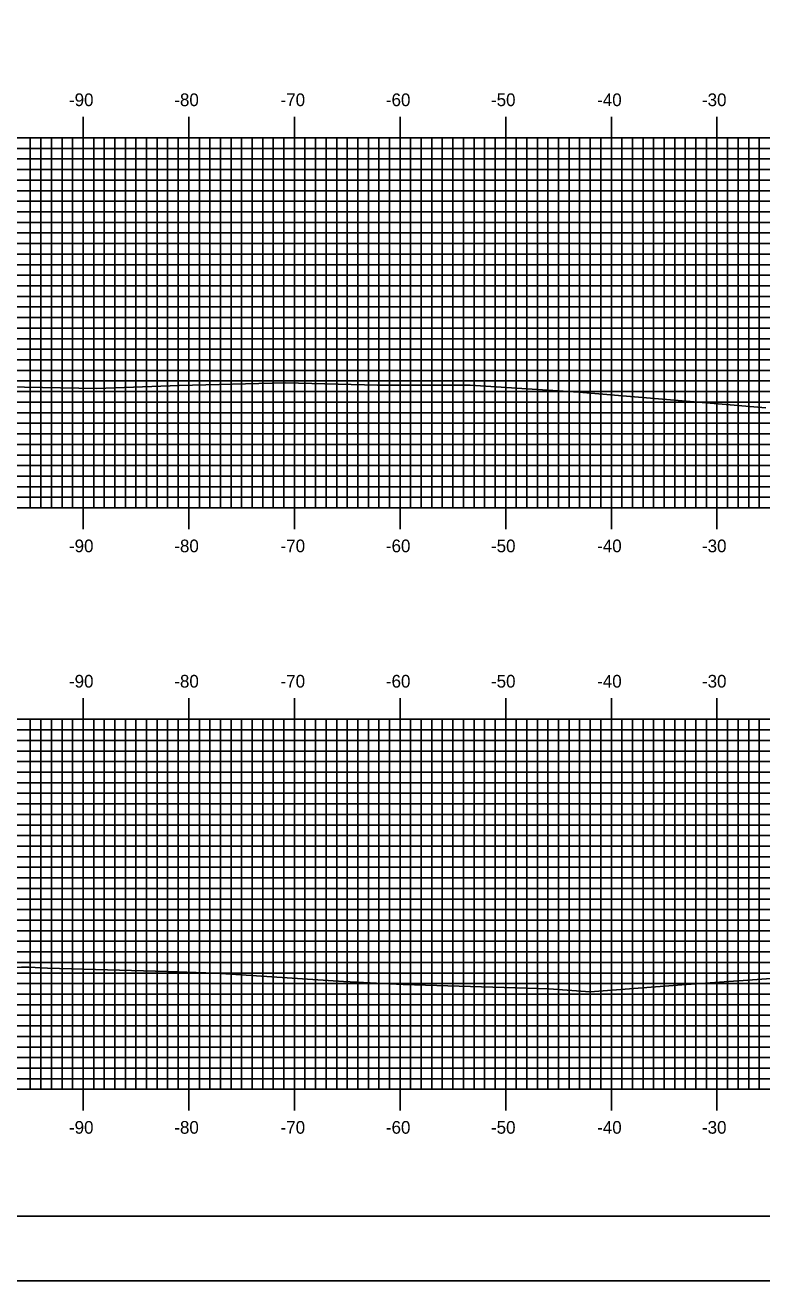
# Model space of a CAD drawing. Extents: x 853329 to 853673, y 364366 to 364586.
# Drawn here: x 853399.7 to 853469.5, y 364365.7 to 364484.5 of the extents above; entities that cross this region are included whole.
import ezdxf

# ---------------------------------------------------------------- set-up
doc = ezdxf.new("R2010")
doc.units = 0
for name, color, linetype in [('BORDER', 7, 'Continuous'), ('H_V ANNOTATION', 7, 'Continuous'), ('MAJOR', 7, 'Continuous'), ('MINOR', 7, 'Continuous'), ('PLOT BOUNDARY', 7, 'Continuous'), ('S_Roadway_Centerline', 7, 'Continuous')]:
    doc.layers.add(name, color=color, linetype=linetype)

msp = doc.modelspace()

# ---------------------------------------------------------------- linework, layer by layer
at = {"layer": 'BORDER'}
msp.add_lwpolyline([(853345.6, 364371.79), (853665.6, 364371.79), (853665.6, 364581.79), (853345.6, 364581.79)], close=True, dxfattribs=at)
at = {"layer": 'MAJOR'}
for p, q in [((853405.2, 364475.79), (853405.2, 364473.79)), ((853415.2, 364475.79), (853415.2, 364473.79)), ((853425.2, 364475.79), (853425.2, 364473.79)), ((853435.2, 364475.79), (853435.2, 364473.79)), ((853445.2, 364475.79), (853445.2, 364473.79)), ((853455.2, 364475.79), (853455.2, 364473.79)), ((853465.2, 364475.79), (853465.2, 364473.79)), ((853355.2, 364473.79), (853635.2, 364473.79)), ((853355.2, 364473.79), (853635.2, 364473.79)), ((853405.2, 364438.79), (853405.2, 364473.79)), ((853415.2, 364438.79), (853415.2, 364473.79)), ((853425.2, 364438.79), (853425.2, 364473.79)), ((853435.2, 364438.79), (853435.2, 364473.79)), ((853445.2, 364438.79), (853445.2, 364473.79)), ((853455.2, 364438.79), (853455.2, 364473.79)), ((853465.2, 364438.79), (853465.2, 364473.79)), ((853355.2, 364468.79), (853635.2, 364468.79)), ((853355.2, 364463.79), (853635.2, 364463.79)), ((853355.2, 364458.79), (853635.2, 364458.79)), ((853355.2, 364453.79), (853635.2, 364453.79)), ((853355.2, 364448.79), (853635.2, 364448.79)), ((853355.2, 364443.79), (853635.2, 364443.79)), ((853355.2, 364438.79), (853635.2, 364438.79)), ((853355.2, 364438.79), (853635.2, 364438.79)), ((853405.2, 364436.78), (853405.2, 364438.79)), ((853415.2, 364436.78), (853415.2, 364438.79)), ((853425.2, 364436.78), (853425.2, 364438.79)), ((853435.2, 364436.78), (853435.2, 364438.79)), ((853445.2, 364436.78), (853445.2, 364438.79)), ((853455.2, 364436.78), (853455.2, 364438.79)), ((853465.2, 364436.78), (853465.2, 364438.79)), ((853405.2, 364420.79), (853405.2, 364418.79)), ((853415.2, 364420.79), (853415.2, 364418.79)), ((853425.2, 364420.79), (853425.2, 364418.79)), ((853435.2, 364420.79), (853435.2, 364418.79)), ((853445.2, 364420.79), (853445.2, 364418.79)), ((853455.2, 364420.79), (853455.2, 364418.79)), ((853465.2, 364420.79), (853465.2, 364418.79)), ((853355.2, 364418.79), (853635.2, 364418.79)), ((853355.2, 364418.79), (853635.2, 364418.79)), ((853405.2, 364383.79), (853405.2, 364418.79)), ((853415.2, 364383.79), (853415.2, 364418.79)), ((853425.2, 364383.79), (853425.2, 364418.79)), ((853435.2, 364383.79), (853435.2, 364418.79)), ((853445.2, 364383.79), (853445.2, 364418.79)), ((853455.2, 364383.79), (853455.2, 364418.79)), ((853465.2, 364383.79), (853465.2, 364418.79)), ((853355.2, 364413.79), (853635.2, 364413.79)), ((853355.2, 364408.79), (853635.2, 364408.79)), ((853355.2, 364403.79), (853635.2, 364403.79)), ((853355.2, 364398.79), (853635.2, 364398.79)), ((853355.2, 364393.79), (853635.2, 364393.79)), ((853355.2, 364388.79), (853635.2, 364388.79)), ((853355.2, 364383.79), (853635.2, 364383.79)), ((853355.2, 364383.79), (853635.2, 364383.79)), ((853405.2, 364381.78), (853405.2, 364383.79)), ((853415.2, 364381.78), (853415.2, 364383.79)), ((853425.2, 364381.78), (853425.2, 364383.79)), ((853435.2, 364381.78), (853435.2, 364383.79)), ((853445.2, 364381.78), (853445.2, 364383.79)), ((853455.2, 364381.78), (853455.2, 364383.79)), ((853465.2, 364381.78), (853465.2, 364383.79))]:
    msp.add_line(p, q, dxfattribs=at)
at = {"layer": 'MINOR'}
for p, q in [((853400.2, 364438.79), (853400.2, 364473.79)), ((853401.2, 364438.79), (853401.2, 364473.79)), ((853402.2, 364438.79), (853402.2, 364473.79)), ((853403.2, 364438.79), (853403.2, 364473.79)), ((853404.2, 364438.79), (853404.2, 364473.79)), ((853406.2, 364438.79), (853406.2, 364473.79)), ((853407.2, 364438.79), (853407.2, 364473.79)), ((853408.2, 364438.79), (853408.2, 364473.79)), ((853409.2, 364438.79), (853409.2, 364473.79)), ((853410.2, 364438.79), (853410.2, 364473.79)), ((853411.2, 364438.79), (853411.2, 364473.79)), ((853412.2, 364438.79), (853412.2, 364473.79)), ((853413.2, 364438.79), (853413.2, 364473.79)), ((853414.2, 364438.79), (853414.2, 364473.79)), ((853416.2, 364438.79), (853416.2, 364473.79)), ((853417.2, 364438.79), (853417.2, 364473.79)), ((853418.2, 364438.79), (853418.2, 364473.79)), ((853419.2, 364438.79), (853419.2, 364473.79)), ((853420.2, 364438.79), (853420.2, 364473.79)), ((853421.2, 364438.79), (853421.2, 364473.79)), ((853422.2, 364438.79), (853422.2, 364473.79)), ((853423.2, 364438.79), (853423.2, 364473.79)), ((853424.2, 364438.79), (853424.2, 364473.79)), ((853426.2, 364438.79), (853426.2, 364473.79)), ((853427.2, 364438.79), (853427.2, 364473.79)), ((853428.2, 364438.79), (853428.2, 364473.79)), ((853429.2, 364438.79), (853429.2, 364473.79)), ((853430.2, 364438.79), (853430.2, 364473.79)), ((853431.2, 364438.79), (853431.2, 364473.79)), ((853432.2, 364438.79), (853432.2, 364473.79)), ((853433.2, 364438.79), (853433.2, 364473.79)), ((853434.2, 364438.79), (853434.2, 364473.79)), ((853436.2, 364438.79), (853436.2, 364473.79)), ((853437.2, 364438.79), (853437.2, 364473.79)), ((853438.2, 364438.79), (853438.2, 364473.79)), ((853439.2, 364438.79), (853439.2, 364473.79)), ((853440.2, 364438.79), (853440.2, 364473.79)), ((853441.2, 364438.79), (853441.2, 364473.79)), ((853442.2, 364438.79), (853442.2, 364473.79)), ((853443.2, 364438.79), (853443.2, 364473.79)), ((853444.2, 364438.79), (853444.2, 364473.79)), ((853446.2, 364438.79), (853446.2, 364473.79)), ((853447.2, 364438.79), (853447.2, 364473.79)), ((853448.2, 364438.79), (853448.2, 364473.79)), ((853449.2, 364438.79), (853449.2, 364473.79)), ((853450.2, 364438.79), (853450.2, 364473.79)), ((853451.2, 364438.79), (853451.2, 364473.79)), ((853452.2, 364438.79), (853452.2, 364473.79)), ((853453.2, 364438.79), (853453.2, 364473.79)), ((853454.2, 364438.79), (853454.2, 364473.79)), ((853456.2, 364438.79), (853456.2, 364473.79)), ((853457.2, 364438.79), (853457.2, 364473.79)), ((853458.2, 364438.79), (853458.2, 364473.79)), ((853459.2, 364438.79), (853459.2, 364473.79)), ((853460.2, 364438.79), (853460.2, 364473.79)), ((853461.2, 364438.79), (853461.2, 364473.79)), ((853462.2, 364438.79), (853462.2, 364473.79)), ((853463.2, 364438.79), (853463.2, 364473.79)), ((853464.2, 364438.79), (853464.2, 364473.79)), ((853466.2, 364438.79), (853466.2, 364473.79)), ((853467.2, 364438.79), (853467.2, 364473.79)), ((853468.2, 364438.79), (853468.2, 364473.79)), ((853469.2, 364438.79), (853469.2, 364473.79)), ((853355.2, 364472.79), (853635.2, 364472.79)), ((853355.2, 364471.79), (853635.2, 364471.79)), ((853355.2, 364470.79), (853635.2, 364470.79)), ((853355.2, 364469.79), (853635.2, 364469.79)), ((853355.2, 364467.79), (853635.2, 364467.79)), ((853355.2, 364466.79), (853635.2, 364466.79)), ((853355.2, 364465.79), (853635.2, 364465.79)), ((853355.2, 364464.79), (853635.2, 364464.79)), ((853355.2, 364462.79), (853635.2, 364462.79)), ((853355.2, 364461.79), (853635.2, 364461.79)), ((853355.2, 364460.79), (853635.2, 364460.79)), ((853355.2, 364459.79), (853635.2, 364459.79)), ((853355.2, 364457.79), (853635.2, 364457.79)), ((853355.2, 364456.79), (853635.2, 364456.79)), ((853355.2, 364455.79), (853635.2, 364455.79)), ((853355.2, 364454.79), (853635.2, 364454.79)), ((853355.2, 364452.79), (853635.2, 364452.79)), ((853355.2, 364451.79), (853635.2, 364451.79)), ((853355.2, 364450.79), (853635.2, 364450.79)), ((853355.2, 364449.79), (853635.2, 364449.79)), ((853355.2, 364447.79), (853635.2, 364447.79)), ((853355.2, 364446.79), (853635.2, 364446.79)), ((853355.2, 364445.79), (853635.2, 364445.79)), ((853355.2, 364444.79), (853635.2, 364444.79)), ((853355.2, 364442.79), (853635.2, 364442.79)), ((853355.2, 364441.79), (853635.2, 364441.79)), ((853355.2, 364440.79), (853635.2, 364440.79)), ((853355.2, 364439.79), (853635.2, 364439.79)), ((853355.2, 364417.79), (853635.2, 364417.79)), ((853400.2, 364383.79), (853400.2, 364418.79)), ((853401.2, 364383.79), (853401.2, 364418.79)), ((853402.2, 364383.79), (853402.2, 364418.79)), ((853403.2, 364383.79), (853403.2, 364418.79)), ((853404.2, 364383.79), (853404.2, 364418.79)), ((853406.2, 364383.79), (853406.2, 364418.79)), ((853407.2, 364383.79), (853407.2, 364418.79)), ((853408.2, 364383.79), (853408.2, 364418.79)), ((853409.2, 364383.79), (853409.2, 364418.79)), ((853410.2, 364383.79), (853410.2, 364418.79)), ((853411.2, 364383.79), (853411.2, 364418.79)), ((853412.2, 364383.79), (853412.2, 364418.79)), ((853413.2, 364383.79), (853413.2, 364418.79)), ((853414.2, 364383.79), (853414.2, 364418.79)), ((853416.2, 364383.79), (853416.2, 364418.79)), ((853417.2, 364383.79), (853417.2, 364418.79)), ((853418.2, 364383.79), (853418.2, 364418.79)), ((853419.2, 364383.79), (853419.2, 364418.79)), ((853420.2, 364383.79), (853420.2, 364418.79)), ((853421.2, 364383.79), (853421.2, 364418.79)), ((853422.2, 364383.79), (853422.2, 364418.79)), ((853423.2, 364383.79), (853423.2, 364418.79)), ((853424.2, 364383.79), (853424.2, 364418.79)), ((853426.2, 364383.79), (853426.2, 364418.79)), ((853427.2, 364383.79), (853427.2, 364418.79)), ((853428.2, 364383.79), (853428.2, 364418.79)), ((853429.2, 364383.79), (853429.2, 364418.79)), ((853430.2, 364383.79), (853430.2, 364418.79)), ((853431.2, 364383.79), (853431.2, 364418.79)), ((853432.2, 364383.79), (853432.2, 364418.79)), ((853433.2, 364383.79), (853433.2, 364418.79)), ((853434.2, 364383.79), (853434.2, 364418.79)), ((853436.2, 364383.79), (853436.2, 364418.79)), ((853437.2, 364383.79), (853437.2, 364418.79)), ((853438.2, 364383.79), (853438.2, 364418.79)), ((853439.2, 364383.79), (853439.2, 364418.79)), ((853440.2, 364383.79), (853440.2, 364418.79)), ((853441.2, 364383.79), (853441.2, 364418.79)), ((853442.2, 364383.79), (853442.2, 364418.79)), ((853443.2, 364383.79), (853443.2, 364418.79)), ((853444.2, 364383.79), (853444.2, 364418.79)), ((853446.2, 364383.79), (853446.2, 364418.79)), ((853447.2, 364383.79), (853447.2, 364418.79)), ((853448.2, 364383.79), (853448.2, 364418.79)), ((853449.2, 364383.79), (853449.2, 364418.79)), ((853450.2, 364383.79), (853450.2, 364418.79)), ((853451.2, 364383.79), (853451.2, 364418.79)), ((853452.2, 364383.79), (853452.2, 364418.79)), ((853453.2, 364383.79), (853453.2, 364418.79)), ((853454.2, 364383.79), (853454.2, 364418.79)), ((853456.2, 364383.79), (853456.2, 364418.79)), ((853457.2, 364383.79), (853457.2, 364418.79)), ((853458.2, 364383.79), (853458.2, 364418.79)), ((853459.2, 364383.79), (853459.2, 364418.79)), ((853460.2, 364383.79), (853460.2, 364418.79)), ((853461.2, 364383.79), (853461.2, 364418.79)), ((853462.2, 364383.79), (853462.2, 364418.79)), ((853463.2, 364383.79), (853463.2, 364418.79)), ((853464.2, 364383.79), (853464.2, 364418.79)), ((853466.2, 364383.79), (853466.2, 364418.79)), ((853467.2, 364383.79), (853467.2, 364418.79)), ((853468.2, 364383.79), (853468.2, 364418.79)), ((853469.2, 364383.79), (853469.2, 364418.79)), ((853355.2, 364416.79), (853635.2, 364416.79)), ((853355.2, 364415.79), (853635.2, 364415.79)), ((853355.2, 364414.79), (853635.2, 364414.79)), ((853355.2, 364412.79), (853635.2, 364412.79)), ((853355.2, 364411.79), (853635.2, 364411.79)), ((853355.2, 364410.79), (853635.2, 364410.79)), ((853355.2, 364409.79), (853635.2, 364409.79)), ((853355.2, 364407.79), (853635.2, 364407.79)), ((853355.2, 364406.79), (853635.2, 364406.79)), ((853355.2, 364405.79), (853635.2, 364405.79)), ((853355.2, 364404.79), (853635.2, 364404.79)), ((853355.2, 364402.79), (853635.2, 364402.79)), ((853355.2, 364401.79), (853635.2, 364401.79)), ((853355.2, 364400.79), (853635.2, 364400.79)), ((853355.2, 364399.79), (853635.2, 364399.79)), ((853355.2, 364397.79), (853635.2, 364397.79)), ((853355.2, 364396.79), (853635.2, 364396.79)), ((853355.2, 364395.79), (853635.2, 364395.79)), ((853355.2, 364394.79), (853635.2, 364394.79)), ((853355.2, 364392.79), (853635.2, 364392.79)), ((853355.2, 364391.79), (853635.2, 364391.79)), ((853355.2, 364390.79), (853635.2, 364390.79)), ((853355.2, 364389.79), (853635.2, 364389.79)), ((853355.2, 364387.79), (853635.2, 364387.79)), ((853355.2, 364386.79), (853635.2, 364386.79)), ((853355.2, 364385.79), (853635.2, 364385.79)), ((853355.2, 364384.79), (853635.2, 364384.79))]:
    msp.add_line(p, q, dxfattribs=at)
at = {"layer": 'PLOT BOUNDARY'}
msp.add_lwpolyline([(853329.42, 364365.67), (853669.42, 364365.67), (853669.42, 364585.67), (853329.42, 364585.67)], close=True, dxfattribs=at)
at = {"layer": 'S_Roadway_Centerline'}
for points in [[(853355.2, 364450.2), (853361.24, 364450.38), (853368.97, 364450.51), (853375.26, 364450.52), (853387.79, 364450.39), (853396.17, 364450.26), (853406.5, 364450.07), (853414.3, 364450.35), (853424.36, 364450.61), (853433.05, 364450.39), (853441.83, 364450.4), (853452.13, 364449.72), (853469.83, 364448.24)], [(853355.2, 364395.05), (853362.38, 364394.85), (853364, 364394.9), (853366.27, 364394.85), (853380.9, 364395), (853388.13, 364395.04), (853399.37, 364395.34), (853400.05, 364395.34), (853401.83, 364395.26), (853413.18, 364394.93), (853417.74, 364394.77), (853429.84, 364393.98), (853435.5, 364393.7), (853449.28, 364393.29), (853453.21, 364393.02), (853461.87, 364393.67), (853472.58, 364394.44)]]:
    msp.add_lwpolyline(points, dxfattribs=at)

# ---------------------------------------------------------------- texts
at = {"layer": 'H_V ANNOTATION'}
for s, p in [('-90', (853403.86, 364476.79)), ('-80', (853413.83, 364476.79)), ('-70', (853423.89, 364476.79)), ('-60', (853433.86, 364476.79)), ('-50', (853443.81, 364476.79)), ('-40', (853453.86, 364476.79)), ('-30', (853463.78, 364476.79)), ('-90', (853403.86, 364434.59)), ('-80', (853413.83, 364434.59)), ('-70', (853423.89, 364434.59)), ('-60', (853433.86, 364434.59)), ('-50', (853443.81, 364434.59)), ('-40', (853453.86, 364434.59)), ('-30', (853463.78, 364434.59)), ('-90', (853403.86, 364421.79)), ('-80', (853413.83, 364421.79)), ('-70', (853423.89, 364421.79)), ('-60', (853433.86, 364421.79)), ('-50', (853443.81, 364421.79)), ('-40', (853453.86, 364421.79)), ('-30', (853463.78, 364421.79)), ('-90', (853403.86, 364379.59)), ('-80', (853413.83, 364379.59)), ('-70', (853423.89, 364379.59)), ('-60', (853433.86, 364379.59)), ('-50', (853443.81, 364379.59)), ('-40', (853453.86, 364379.59)), ('-30', (853463.78, 364379.59))]:
    msp.add_text(s, height=1.2, dxfattribs=at).set_placement(p)

doc.saveas('drawing.dxf')
